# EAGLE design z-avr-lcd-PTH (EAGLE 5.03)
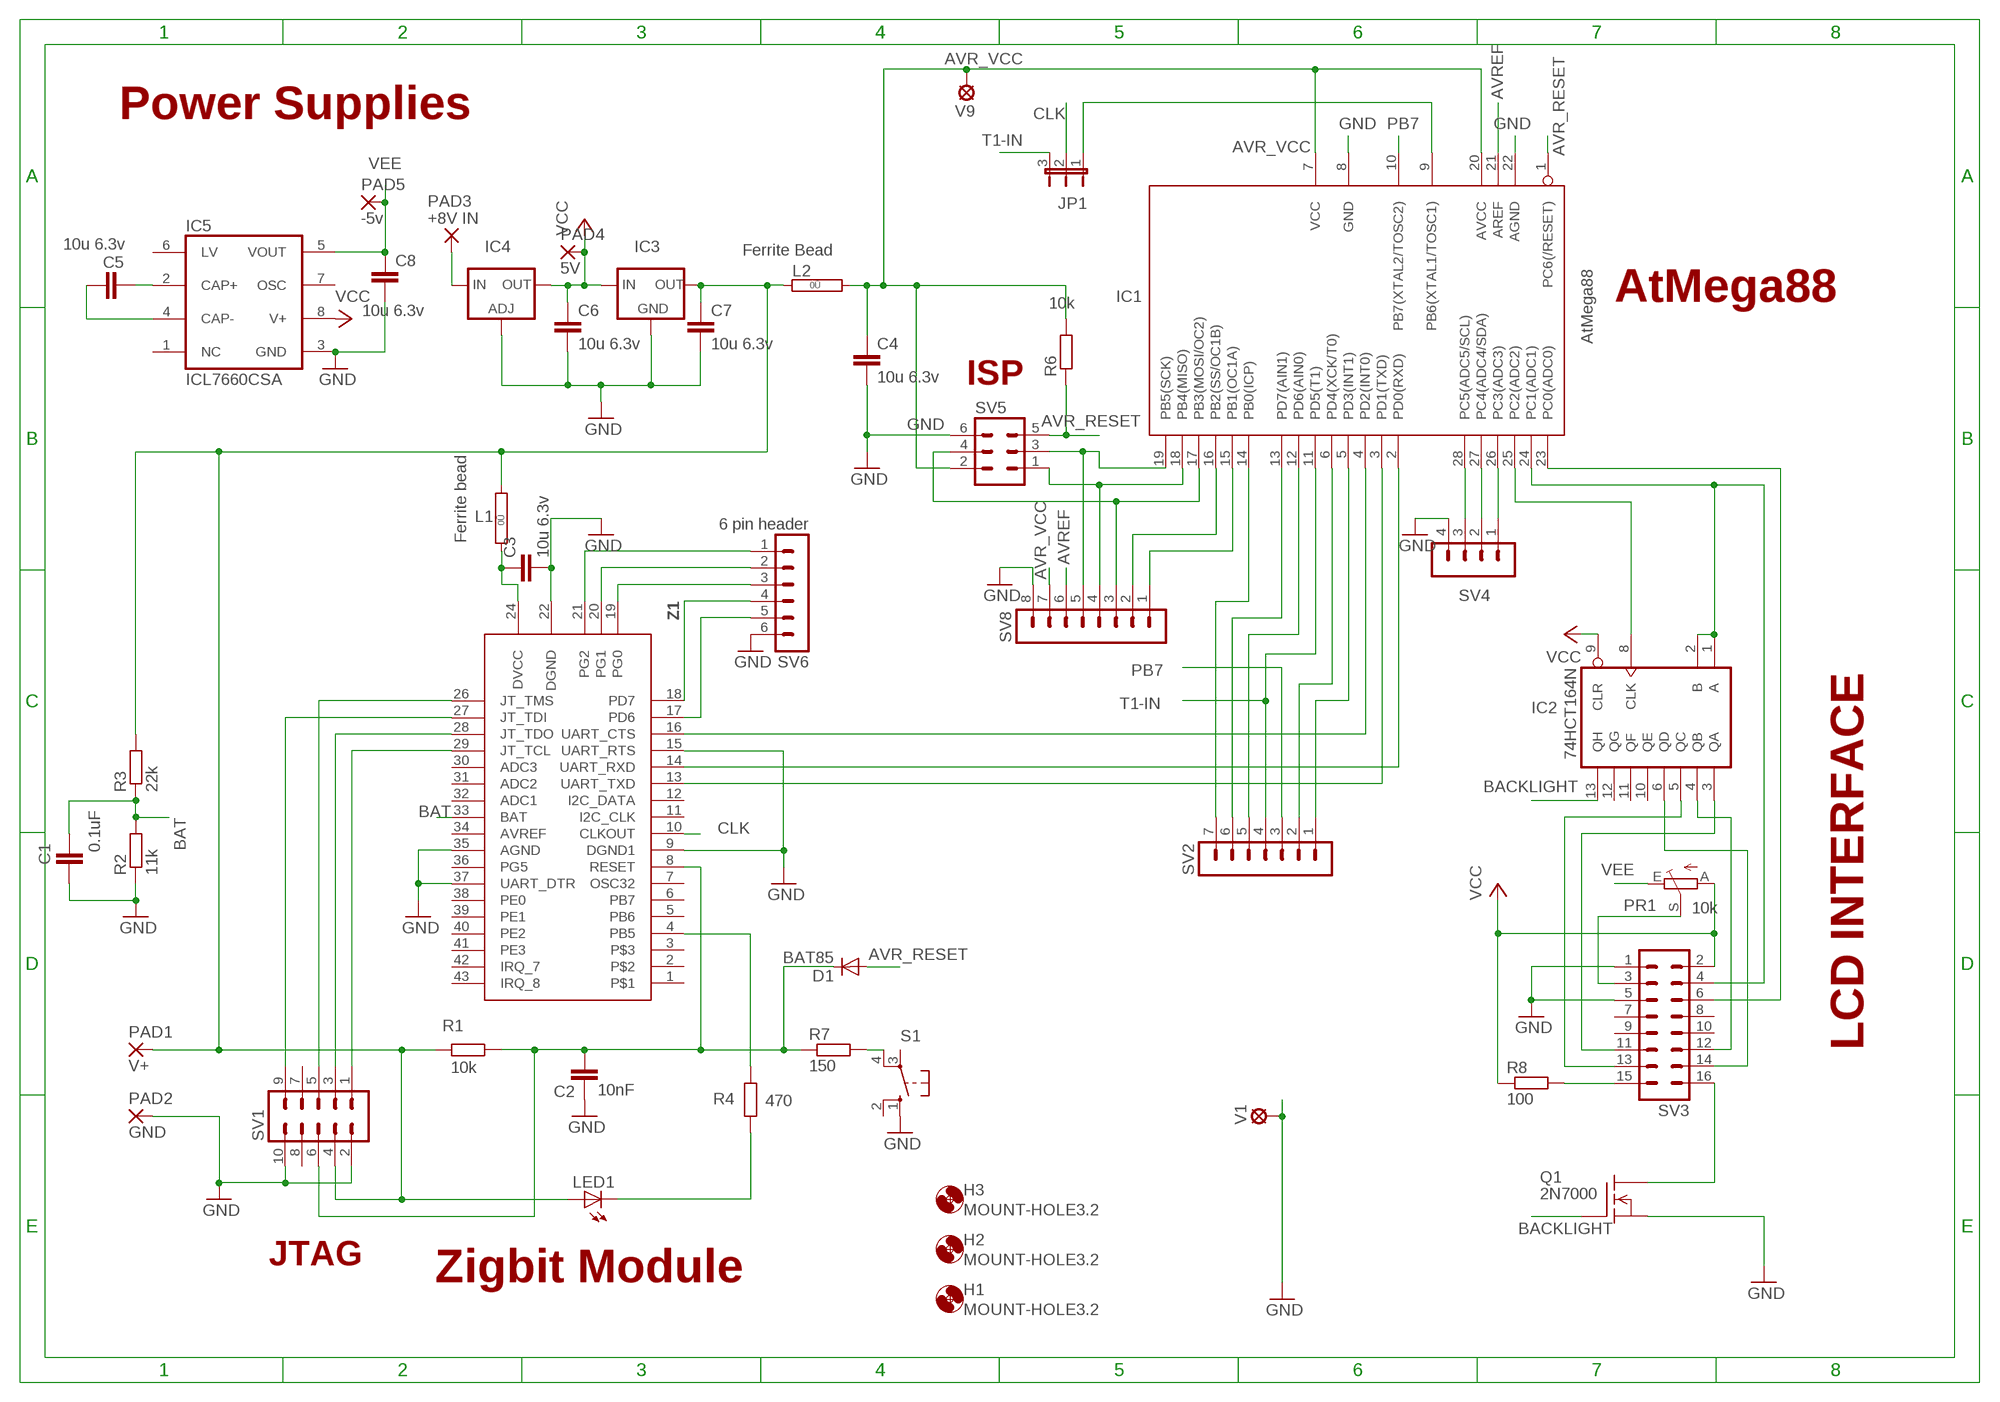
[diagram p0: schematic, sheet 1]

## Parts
C1  0.1uF  C5P  [C050-030-075]
C2  10nF  C5P  [C050-030-075]
C3  10u 6.3v  C-EUC1206  [C1206]
C4  10u 6.3v  C-EUC1206  [C1206]
C5  10u 6.3v  C-EUC1206  [C1206]
C6  10u 6.3v  C-EUC1206  [C1206]
C7  10u 6.3v  C-EUC1206  [C1206]
C8  10u 6.3v  C-EUC1206  [C1206]
D1  BAT85  1N4148  [DO34-7]
H1  MOUNT-HOLE3.2  [3,2]
H2  MOUNT-HOLE3.2  [3,2]
H3  MOUNT-HOLE3.2  [3,2]
IC1  AtMega88  MEGA8-P  [DIL28-3]
IC2  74HCT164N  74ACT164N  [DIL14]
IC3  MC1702-3302E/TO 3.3V LDO VREG  XC63FPT  [TO92]
IC4  LD117ADT50TR  [DPACK]
IC5  ICL7660CSA  [SO08]
JP1  3 way Jumper  JP2E  [JP2]
L1  Ferrite bead  0R  [0R/10]
L2  Ferrite Bead  JUMPER_0R  [JUMPER_0R/10]
LED1  3MM red LED  LED-3MM3MM  [HLMP-D105]
PAD1  V+  TERMINAL-PAD  [2,54/1,1]
PAD2  GND  TERMINAL-PAD  [2,54/1,1]
PAD3  +8V IN  PAD-TERMINAL  [2,54/1,1]
PAD4  5V  TERMINAL-PAD  [2,54/1,1]
PAD5  -5v  TERMINAL-PAD  [2,54/1,1]
PR1  10k  VAR_RESISTOR_TRIMS63P  [S63P]
Q1  2N7000  [TO92]
R1  10k  R  [0207/10]
R2  11k  R  [0207/10]
R3  22k  R  [0207/10]
R4  470  R  [0207/10]
R6  10k  R  [0207/10]
R7  150  R  [0207/10]
R8  100  R  [0207/10]
S1  BW3-1000 PCB pushbutton  10-XX  [B3F-10XX]
SV1  10 way IDC male horiz mnt  ML10L  [ML10L]
SV2  7 way pin header  MA07-1  [MA07-1]
SV3  16 way IDC male horiz mnt  ML16L  [ML16L]
SV4  4 way pin header  MA04-1  [MA04-1]
SV5  6 way male IDC horiz mnt  ML6L  [ML6L]
SV6  6 pin header  MA06-1  [MA06-1]
SV8  8 way pin header  MA08-1  [MA08-1]
V1  HOLE-VIA"  [1,6/0,8]
V9  HOLE-VIA"  [1,6/0,8]
Z1  ZDM-A1281-A2N  [ZIGSMD]

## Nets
AVR_RESET: D1.A IC1.1(PC6(/RESET)) R6.1 SV5.5
AVR_VCC [supply]: C4.1 IC1.7(VCC) IC1.20(AVCC) L2.2 R6.2 SV5.2 SV8.7 V9.1(MP)
AVREF: IC1.21(AREF) SV8.6
BACKLIGHT: IC2.13(QH) Q1.2(G)
BAT: C1.2 R2.2 R3.1 Z1.33(BAT)
CLK: JP1.2 Z1.10(CLKOUT)
GND: C1.1 C2.1 C3.2 C4.2 C6.2 C7.2 C8.2 IC1.8(GND) IC1.22(AGND) IC3.1(GND) IC4.1(ADJ) IC5.3(GND) PAD2.1(P) Q1.3(S) R2.1 S1.1(S) SV1.2 SV1.10 SV3.1 SV3.5 SV4.4 SV5.6 SV6.6 SV8.8 V1.1(MP) Z1.9(DGND1) Z1.15(UART_RTS) Z1.22(DGND) Z1.35(AGND) Z1.37(UART_DTR)
N$1: IC1.18(PB4(MISO)) SV5.1 SV8.4
N$2: IC1.19(PB5(SCK)) SV5.3 SV8.5
N$3: IC1.24(PC1(ADC1)) IC2.1(A) IC2.2(B) SV3.4
N$4: IC1.25(PC2(ADC2)) IC2.8(CLK)
N$5: IC1.28(PC5(ADC5/SCL)) SV4.3
N$6: R7.2 S1.4(P1)
N$7: IC1.27(PC4(ADC4/SDA)) SV4.2
N$8: IC1.17(PB3(MOSI/OC2)) SV5.4 SV8.3
N$9: SV1.5 Z1.26(JT_TMS)
N$10: SV1.1 Z1.29(JT_TCL)
N$11: SV1.3 Z1.28(JT_TDO)
N$12: IC1.26(PC3(ADC3)) SV4.1
N$13: C2.2 D1.C R1.2 R7.1 SV1.6 Z1.8(RESET)
N$14: IC2.6(QD) SV3.14
N$15: IC1.23(PC0(ADC0)) SV3.6
N$16 [supply]: C7.1 IC3.3(OUT) L1.2 L2.1 LED1.A PAD1.1(P) R1.1 R3.2 SV1.4
N$17: C5.1 IC5.2(CAP+)
N$18: IC1.4(PD2(INT0)) Z1.16(UART_CTS)
N$19: PR1.S SV3.3
N$20: IC1.2(PD0(RXD)) Z1.14(UART_RXD)
N$21: IC1.3(PD1(TXD)) Z1.13(UART_TXD)
N$22: IC2.3(QA) SV3.11
N$23: IC2.4(QB) SV3.12
N$24: IC2.5(QC) SV3.13
N$25: C5.2 IC5.4(CAP-)
N$26: R8.2 SV3.15
N$27: Q1.1(D) SV3.16
N$28: R4.2 Z1.4(PB5)
N$29 [supply]: IC4.3(IN) PAD3.1(P)
N$30: LED1.K(C) R4.1
N$31: SV1.9 Z1.27(JT_TDI)
N$32: IC1.9(PB6(XTAL1/TOSC1)) JP1.1
N$33 [supply]: C3.1 L1.1 Z1.24(DVCC)
N$34: SV6.1 Z1.21(PG2)
N$35: SV6.2 Z1.20(PG1)
N$36: SV6.3 Z1.19(PG0)
N$37: IC1.5(PD3(INT1)) SV2.1
N$38: IC1.15(PB1(OC1A)) SV8.1
N$39: IC1.16(PB2(SS/OC1B)) SV8.2
N$40: IC1.12(PD6(AIN0)) SV2.5
N$41: IC1.13(PD7(AIN1)) SV2.6
N$42: IC1.14(PB0(ICP)) SV2.7
N$43: SV6.4 Z1.18(PD7)
N$44: IC1.6(PD4(XCK/T0)) SV2.2
N$45: SV6.5 Z1.17(PD6)
PB7: IC1.10(PB7(XTAL2/TOSC2)) SV2.3
T1-IN: IC1.11(PD5(T1)) JP1.3 SV2.4
VCC [supply]: C6.1 IC2.9(CLR) IC3.2(IN) IC4.4(OUT) IC5.8(V+) PAD4.1(P) PR1.A R8.1 SV3.2
VEE: C8.1 IC5.5(VOUT) PAD5.1(P) PR1.E
Unconnected: IC2.10(QE) IC2.11(QF) IC2.12(QG) IC5.1(NC) IC5.6(LV) IC5.7(OSC) S1.2(S1) S1.3(P) SV1.7 SV1.8 SV3.7 SV3.8 SV3.9 SV3.10 Z1.1 Z1.2 Z1.3 Z1.5(PB6) Z1.6(PB7) Z1.7(OSC32) Z1.11(I2C_CLK) Z1.12(I2C_DATA) Z1.30(ADC3) Z1.31(ADC2) Z1.32(ADC1) Z1.34(AVREF) Z1.36(PG5) Z1.38(PE0) Z1.39(PE1) Z1.40(PE2) Z1.41(PE3) Z1.42(IRQ_7) Z1.43(IRQ_8)

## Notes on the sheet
- Power Supplies
- AtMega88
- ISP
- LCD INTERFACE
- JTAG
- Zigbit Module

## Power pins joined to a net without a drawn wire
GND: IC2.7(GND)
VCC: IC2.14(VCC)

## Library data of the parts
C1 C2 = ee2parts:C: Capacitor
C3-C8 = rcl:C-EU: CAPACITOR, European symbol
D1 = ee2parts:1N4148: DIODE
H1-H3 = holes:MOUNT-HOLE: MOUNTING HOLE with drill center marker
IC1 = atmel:MEGA8-P: MICROCONTROLLER 8 Kbytes FLASH, 1 kbytes SRAM, 512 bytes EEPROM, USART, 4-channel 10 bit ADC, 2-channel 8 bit ADC Pin compatible with Atmega48, ATMega88, ATMega168 Source: avr.lbr
IC2 = 74xx-eu:74*164: 8-bit parallel out SHIFT REGISTER
IC3 = v-reg:XC63FP: Positiv Voltage Regulators www.torex.co.jp/english/product/pro02/pdf/0201_xc62fp.pdf
IC4 = v-reg:LD117A?*: Low drop fixed and adjustable positive voltage regulators 1 A Source: http://www.st.com/stonline/products/literature/ds/7194/ld1117axx.pdf
IC5 = maxim:ICL7660CSA: VOLTAGE CONVERTER
JP1 = jumper:JP2E: JUMPER
L1 = jumper:0R: Bridge 0R 10mm
L2 = z-avr-lcd-noPTH:JUMPER_0R: Bridge 0R 10mm
LED1 = ee2parts:LED-3MM: LED
PAD1 PAD2 PAD4 PAD5 = ee2parts:TERMINAL-PAD: LARGE THROUGH-HOLE PAD
PAD3 = ee2parts:PAD-TERMINAL: LARGE THROUGH-HOLE PAD
PR1 = ee2parts:VAR_RESISTOR_TRIM: Variable resistor / potentiometer Trimmer potentiometer - Note that slider to end makes variable resistance
Q1 = z-avr-lcd-noPTH:2N7000: N-Channel Enhancement MOSFET 200V; 0,16A; 11Ohm
R1-R4 R6-R8 = ee2parts:R: Resistor
S1 = switch-omron:10-XX: OMRON SWITCH
SV1 = con-ml:ML10L: HARTING
SV2 = con-lstb:MA07-1: PIN HEADER
SV3 = con-ml:ML16L: HARTING
SV4 = con-lstb:MA04-1: PIN HEADER
SV5 = con-ml:ML6L: HARTING
SV6 = con-lstb:MA06-1: PIN HEADER
SV8 = con-lstb:MA08-1: PIN HEADER
V1 V9 = ee2parts:HOLE-VIA: FIXED VIA
Z1 = ee2parts:ZDM-A1281-A2

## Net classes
1 supply: width 0.889 mm

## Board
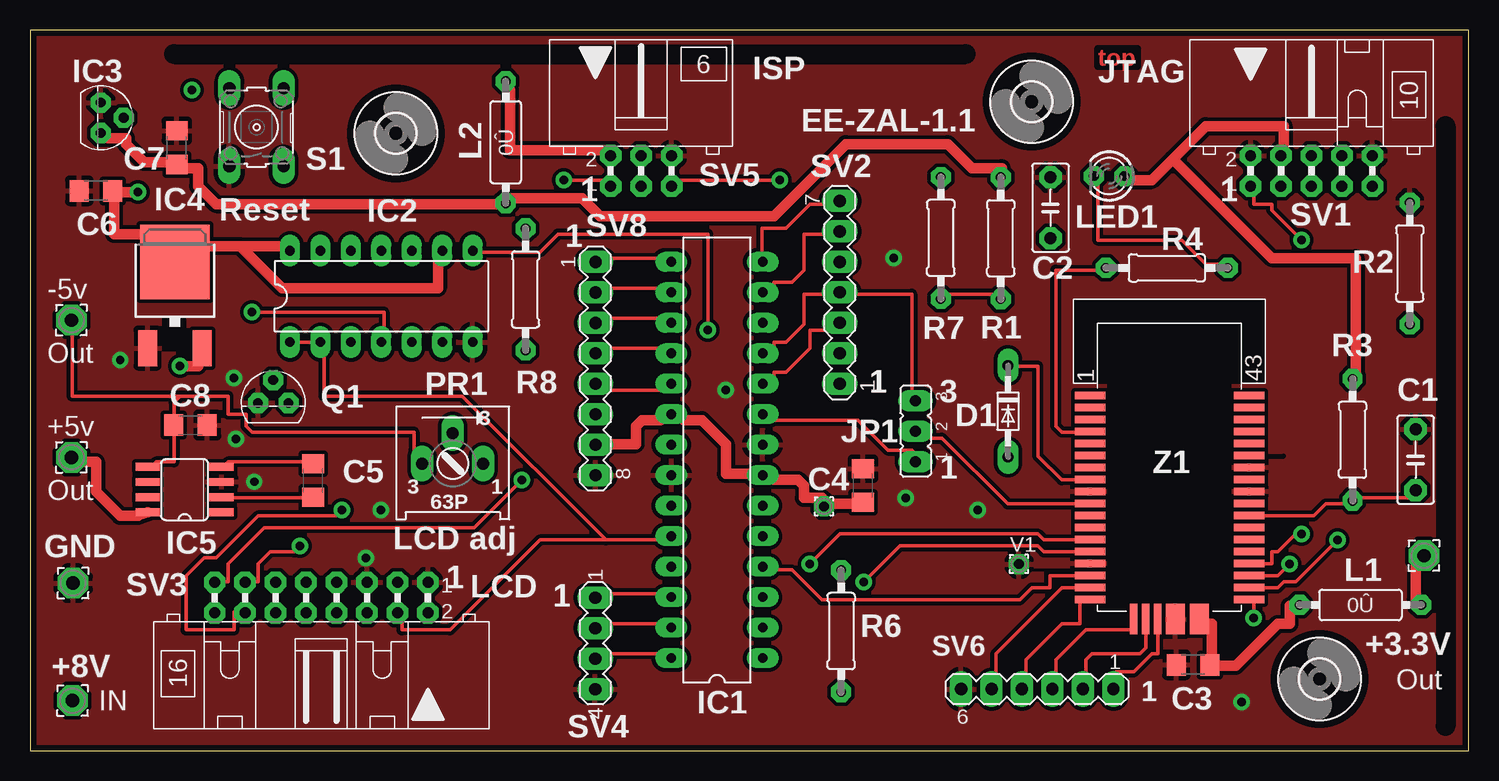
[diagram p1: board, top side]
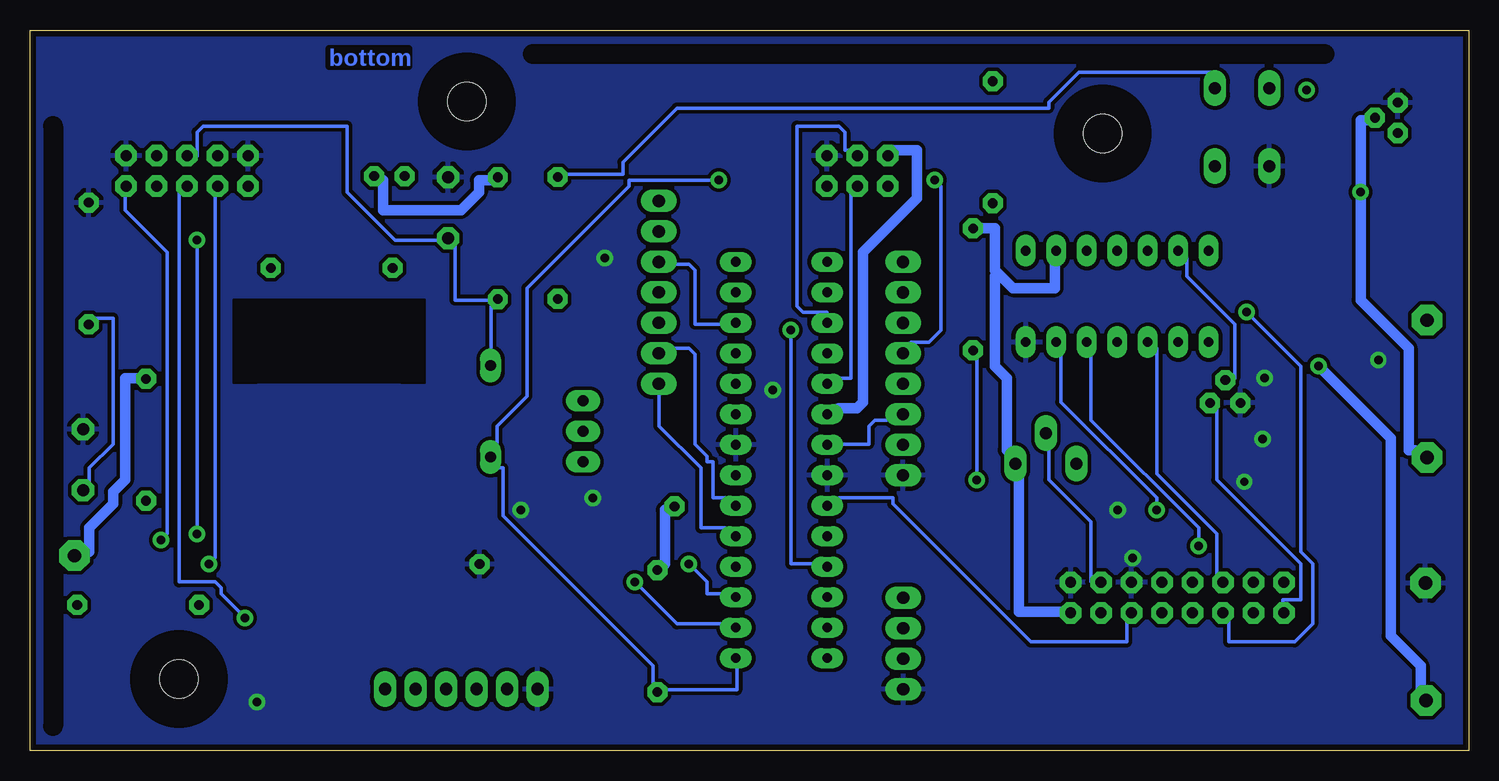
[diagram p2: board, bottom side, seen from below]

Size 119.92 x 60.07 mm. Coordinates in mm from the lower left corner, seen from the top.
Outline: 0,0 119.92,0 119.92,60.07 0,60.07 0,0
Copper layers (1*16): Top 0.035mm / dielectric 1.5mm / Bottom 0.035mm
Design rules "zigbit_rules *": minimum track width 12mil, minimum drill 0.7mm, track to track 12mil, track to pad 12mil, pad to pad 12mil, via to via 12mil, smd to smd 0mil, copper to edge 20mil, drill to drill 10mil, minimum pad ring 17mil, minimum via ring 13mil, stop-mask expansion 0mil, vias tented up to drill 0mil, thermal gap 15mil
tRestrict: area 11,33.3 to 13,36.1; 4 lines
bRestrict: 2 lines

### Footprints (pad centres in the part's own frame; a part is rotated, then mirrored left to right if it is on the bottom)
C050-030-075 = drill 1 octagon: 1 -2.54,0; 2 2.54,0
C1206 = smd 1.6 x 1.8: 1 -1.4,0; 2 1.4,0
DO34-7 = drill 0.9 long: A 3.81,0; C -3.81,0
3,2 = hole 3.2: 0,0
DIL28-3 = drill 0.813 long: 1 -16.51,-3.81; 2 -13.97,-3.81; 3 -11.43,-3.81; 4 -8.89,-3.81; 5 -6.35,-3.81; 6 -3.81,-3.81; 7 -1.27,-3.81; 8 1.27,-3.81; 9 3.81,-3.81; 10 6.35,-3.81; 11 8.89,-3.81; 12 11.43,-3.81; 13 13.97,-3.81; 14 16.51,-3.81; 15 16.51,3.81; 16 13.97,3.81; 17 11.43,3.81; 18 8.89,3.81; 19 6.35,3.81; 20 3.81,3.81; 21 1.27,3.81; 22 -1.27,3.81; 23 -3.81,3.81; 24 -6.35,3.81; 25 -8.89,3.81; 26 -11.43,3.81; 27 -13.97,3.81; 28 -16.51,3.81
DIL14 = drill 0.813 long: 1 -7.62,-3.81; 2 -5.08,-3.81; 3 -2.54,-3.81; 4 0,-3.81; 5 2.54,-3.81; 6 5.08,-3.81; 7 7.62,-3.81; 8 7.62,3.81; 9 5.08,3.81; 10 2.54,3.81; 11 0,3.81; 12 -2.54,3.81; 13 -5.08,3.81; 14 -7.62,3.81
TO92 = drill 0.813 octagon: 1 -1.27,0; 2 0,1.905; 3 1.27,0
DPACK = smd 1.6 x 3: 1 -2.28,-4.8; 3 2.28,-4.8 | smd 5.8 x 6.2: 4 0,2.38
SO08 = smd 0.66 x 2.032: 1 -1.905,-3.073; 2 -0.635,-3.073; 3 0.635,-3.073; 4 1.905,-3.073; 5 1.905,3.073; 6 0.635,3.073; 7 -0.635,3.073; 8 -1.905,3.073
JP2 = drill 0.914 long: 1 -2.54,0; 2 0,0; 3 2.54,0
0R/10 = drill 0.813 pad 1.6 octagon: 1 -5.08,0; 2 5.08,0
JUMPER_0R/10 = drill 0.813 pad 1.6 octagon: 1 -5.08,0; 2 5.08,0
HLMP-D105 = drill 0.8 octagon: A -1.27,0; K 1.27,0
2,54/1,1 = drill 1.118 pad 2.54 octagon: 1 0,0
S63P = drill 1 long: A 2.54,0; E -2.54,0; S 0,2.54
TO92' = drill 0.813 octagon: 1 1.27,0; 2 0,1.905; 3 -1.27,0
0207/10 = drill 0.8 octagon: 1 -5.08,0; 2 5.08,0
B3F-10XX = drill 1.016 long: 1 -3.251,2.261; 2 3.251,2.261; 3 -3.251,-2.261; 4 3.251,-2.261
ML10L = drill 0.914 octagon: 1 -5.08,-1.27; 2 -5.08,1.27; 3 -2.54,-1.27; 4 -2.54,1.27; 5 0,-1.27; 6 0,1.27; 7 2.54,-1.27; 8 2.54,1.27; 9 5.08,-1.27; 10 5.08,1.27
MA07-1 = drill 1.016 long: 1 -7.62,0; 2 -5.08,0; 3 -2.54,0; 4 0,0; 5 2.54,0; 6 5.08,0; 7 7.62,0
ML16L = drill 0.914 octagon: 1 -8.89,-1.27; 2 -8.89,1.27; 3 -6.35,-1.27; 4 -6.35,1.27; 5 -3.81,-1.27; 6 -3.81,1.27; 7 -1.27,-1.27; 8 -1.27,1.27; 9 1.27,-1.27; 10 1.27,1.27; 11 3.81,-1.27; 12 3.81,1.27; 13 6.35,-1.27; 14 6.35,1.27; 15 8.89,-1.27; 16 8.89,1.27
MA04-1 = drill 1.016 long: 1 -3.81,0; 2 -1.27,0; 3 1.27,0; 4 3.81,0
ML6L = drill 0.914 octagon: 1 -2.54,-1.27; 2 -2.54,1.27; 3 0,-1.27; 4 0,1.27; 5 2.54,-1.27; 6 2.54,1.27
MA06-1 = drill 1.016 long: 1 -6.35,0; 2 -3.81,0; 3 -1.27,0; 4 1.27,0; 5 3.81,0; 6 6.35,0
MA08-1 = drill 1.016 long: 1 -8.89,0; 2 -6.35,0; 3 -3.81,0; 4 -1.27,0; 5 1.27,0; 6 3.81,0; 7 6.35,0; 8 8.89,0
1,6/0,8 = drill 0.813 pad 1.6 octagon: 1 0,0
ZIGSMD = smd 0.635 x 2.54: 1 7,6.635; 2 6,6.635; 3 5,6.635; 4 4,6.635; 5 3,6.635; 6 2,6.635; 7 1,6.635; 8 0,6.635; 9 -1,6.635; 10 -2,6.635; 11 -3,6.635; 12 -4,6.635; 13 -5,6.635; 14 -6,6.635; 15 -7,6.635; 16 -8,6.635; 17 -9,6.635; 18 -10,6.635; 26 -10,-6.635; 27 -9,-6.635; 28 -8,-6.635; 29 -7,-6.635; 30 -6,-6.635; 31 -5,-6.635; 32 -4,-6.635; 33 -3,-6.635; 34 -2,-6.635; 35 -1,-6.635; 36 0,-6.635; 37 1,-6.635; 38 2,-6.635; 39 3,-6.635; 40 4,-6.635; 41 5,-6.635; 42 6,-6.635; 43 7,-6.635 | smd 2.54 x 0.635: 19 -11.635,3; 20 -11.635,2; 21 -11.635,1 | smd 2.54 x 1.6: 22 -11.635,-0.5; 24 -11.635,-2.5

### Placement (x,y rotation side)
C1  115.5,24.26 270 top
C2  85.07,45.26 270 top
C3  96.96,7.16 180 top
C4  69.44,22.11 90 top
C5  23.61,22.52 90 top
C6  5.5,46.66 180 top
C7  12.24,50.27 90 top
C8  13.38,27.15 0 top
D1  81.53,28.3 270 top
H1  107.5,5.99 0 top
H2  83.5,54.1 0 top
H3  30.5,51.46 0 top
IC1  57.27,24.24 90 top
IC2  29.29,37.87 0 top
IC3  5.9,52.75 270 top
IC4  12.08,38.35 0 top
IC5  12.89,21.77 90 top
JP1  73.82,26.64 90 top
L1  110.91,12.16 0 top
L2  39.66,50.72 90 top
LED1  89.96,47.89 180 top
PAD1  116.2,16.26 0 top
PAD2  3.59,13.98 90 top
PAD3  3.55,4.18 0 top
PAD4  3.45,24.45 0 top
PAD5  3.45,35.88 0 top
PR1  35.24,23.94 0 top
Q1  2N7000  [TO92']  20.28,28.99 0 top
R1  80.92,42.72 270 top
R2  115.02,40.61 270 top
R3  110.25,25.92 90 top
R4  94.77,40.24 180 top
R6  67.62,9.98 90 top
R7  75.93,42.74 90 top
R8  41.31,38.45 270 top
S1  18.88,51.97 90 top
SV1  106.83,48.33 0 top
SV2  67.51,38.2 90 top
SV3  24.28,12.77 180 top
SV4  47.12,8.95 270 top
SV5  50.95,48.33 0 top
SV6  83.97,5.15 180 top
SV8  47.14,31.85 270 top
V1  82.45,15.56 0 top
V9  66.19,20.37 0 top
Z1  94.99,22.61 90 top

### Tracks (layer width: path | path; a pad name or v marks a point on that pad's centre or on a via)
AVR_RESET  (via drill 0.7)
  Top 0.305: v62.5,47.57 54,47.57 SV5.5
  Bottom 0.305: IC1.1 61,7.07 61,5.07 67,5.07 R6.1 68,5.57 68,7.07 80.5,19.57 80.5,23.57 81,23.57 D1.A 81,25.57 81,27.07 78.5,29.57 78.5,38.57 70,47.07 70,47.57 v62.5,47.57
AVR_VCC
  Top 0.889: L2.2 40,55.07 40,50.07 48,50.07 SV5.2 | SV8.7 48.5,25.57 50.5,25.57 50.5,27.07 51,27.57 52.5,27.57 IC1.20 54.5,27.57 56,27.57 58,25.57 58,23.07 60,23.07 IC1.7 62,22.57 64,22.57 64.5,22.07 64.5,21.07 66,21.07 V9.1 67,20.57 69,20.57 C4.1
  Bottom 0.889: R6.2 67,15.57 67,20.07 V9.1 | SV5.2 48,50.07 46,50.07 46,46.07 50.5,41.57 50.5,29.07 51,28.57 52.5,28.57 IC1.20
AVREF
  Bottom 0.305: IC1.21 52.5,25.57 50,25.57 50,27.07 49.5,27.57 48.5,27.57 SV8.6
BACKLIGHT
  Bottom 0.305: Q1.2 19.5,31.07 19.5,35.57 23.5,39.57 23.5,41.07 IC2.13
BAT
  Top 0.305: Z1.33 102.5,19.57 107,19.57 108,20.57 109.5,20.57 R3.1 111,21.07 115,21.07 C1.2
  Bottom 0.305: R2.2 114.5,36.07 113,36.07 113,25.57 115,23.57 115,22.07 C1.2
CLK
  Top 0.305: Z1.10 87.5,20.57 81.5,20.57 76,26.07 75,26.07 JP1.2
GND  (via drill 0.7)
  other vias: 17.17,25.98 18.69,22.42 7.52,32.58 17,31.07 28,16.07 29.25,20.07 73,21.07 72,41.07 79,20.07 101,4.07 58,30.07
  pour Bottom: 0.25,59.82 119.67,59.82 119.67,0.25 0.25,0.25
  pour Top: 0.25,59.82 119.67,59.82 119.67,0.25 0.25,0.25
N$1  (via drill 0.7)
  Top 0.305: IC1.18 52.5,33.57 48.5,33.57 SV8.4 | v44.5,47.57 48,47.57 SV5.1
  Bottom 0.305: v44.5,47.57 44,47.07 44,35.07 45,34.07 46.5,34.07 46.5,33.57 SV8.4
N$2
  Top 0.305: IC1.19 52.5,30.07 48.5,30.07 SV8.5
  Bottom 0.305: SV5.3 51.5,46.57 51.5,31.07 52.5,31.07 IC1.19
N$3
  Top 0.305: IC2.1 22.5,34.07 23.5,34.07 IC2.2 24.5,33.07 24.5,29.57 36,29.57 48,17.57 | 48,17.57 42.5,17.57 35,10.07 31,10.07 31,11.07 SV3.4 | 48,17.57 52.5,17.57 IC1.24
N$4  (via drill 0.7)
  Top 0.305: v56.5,35.07 56.5,43.07 44,43.07 42.5,41.57 37.5,41.57 IC2.8
  Bottom 0.305: v56.5,35.07 56.5,15.57 54.5,15.57 IC1.25
N$5
  Top 0.305: IC1.28 52.5,8.07 48.5,8.07 SV4.3
N$6
  Bottom 0.305: R7.2 75.5,48.07 70.5,48.07 70.5,49.07 66,53.57 35,53.57 35,54.07 32.5,56.57 21.5,56.57 S1.4
N$7
  Top 0.305: IC1.27 52.5,10.57 48.5,10.57 SV4.2
N$8
  Top 0.305: IC1.17 52.5,36.07 48.5,36.07 SV8.3
  Bottom 0.305: SV5.4 51.5,50.07 52,50.07 52,51.57 52.5,52.07 56,52.07 56,37.07 55.5,36.57 53.5,36.57 53.5,36.07 IC1.17
N$9  (via drill 0.7)
  Top 0.305: v102,11.07 102,12.57 Z1.26
  Bottom 0.305: v102,11.07 104,13.07 104,13.57 104.5,14.07 107.5,14.07 107.5,46.57 SV1.5
N$10  (via drill 0.7)
  Top 0.305: v106,18.07 105.5,18.07 104,16.57 103.5,16.57 103.5,15.57 102.5,15.57 Z1.29 | v106,42.57 103.5,45.07 103.5,45.57 102,45.57 102,46.57 SV1.1
  Bottom 0.305: v106,18.07 v106,42.57
N$11  (via drill 0.7)
  Top 0.305: v105,15.57 104,14.57 102.5,14.57 Z1.28
  Bottom 0.305: v105,15.57 104.5,16.07 104.5,46.57 SV1.3
N$12
  Top 0.305: IC1.26 52.5,13.07 48.5,13.07 SV4.1
N$13
  Top 0.305: R1.2 80.5,38.07 76.5,38.07 R7.1 | Z1.8 87.5,22.57 86,22.57 84,24.57 84,32.07 82,32.07 D1.C
  Bottom 0.305: D1.C 81.5,33.07 81.5,37.07 R1.2 81.5,37.57 84.5,37.57 84.5,42.07 C2.2 86,42.57 89.5,42.57 93.5,46.57 93.5,52.07 105.5,52.07 106,51.57 106,49.57 SV1.6
N$14  (via drill 0.7)
  Top 0.305: v26,20.07 25.5,19.57 19,19.57 15.5,16.07 14.5,16.07 13,14.57 13,10.07 17,10.07 17,11.57 17.5,11.57 SV3.14
  Bottom 0.305: v26,20.07 26,21.07 34,29.07 34,33.07 IC2.6
N$15
  Bottom 0.305: IC1.23 52.5,21.07 48,21.07 48,20.57 36.5,9.07 28.5,9.07 28.5,11.07 SV3.6
N$16
  Top 0.889: IC3.3 6.5,51.07 8,51.07 8,50.57 9.5,49.07 11.5,49.07 C7.1 13,48.57 14,48.57 14,47.07 15.5,45.57 39,45.57 L2.1 40,46.07 46,46.07 47.5,44.57 62,44.57 68,50.57 76.5,50.57 78.5,48.57 81,48.57 R1.1 | L1.2 115.5,12.57 115.5,15.57 PAD1.1 | 95.25,49.32 93.5,47.57 92,47.57 LED1.A | 95.25,49.32 98,52.07 104.5,52.07 104.5,50.07 SV1.4 | R3.2 110.5,31.57 110.5,41.07 103.5,41.07 95.25,49.32
  Bottom 0.889: R3.2 111,31.07 112,31.07 112,22.57 113,21.57 113,20.57 115,18.57 115,16.57 PAD1.1 | R1.1 81.5,47.57 82.5,47.57 82.5,46.57 84,45.07 90.5,45.07 90.5,47.57 LED1.A
N$17
  Top 0.305: C5.1 23,21.07 16.5,21.07 IC5.2
N$18
  Top 0.305: Z1.16 87.5,14.57 85,14.57 85,13.57 83.5,13.57 82.5,12.57 66,12.57 63.5,15.07 62,15.07 IC1.4
N$19
  Bottom 0.305: SV3.3 31.5,14.07 31.5,19.07 35,22.57 35,25.07 PR1.S
N$20  (via drill 0.7)
  Top 0.305: v69.5,14.07 72.5,17.07 84,17.07 84.5,16.57 87.5,16.57 Z1.14
  Bottom 0.305: v69.5,14.07 66,10.57 62,10.57 IC1.2
N$21  (via drill 0.7)
  Top 0.305: v65,15.57 67.5,18.07 84,18.07 84.5,17.57 87.5,17.57 Z1.13
  Bottom 0.305: v65,15.57 63.5,14.07 63.5,13.07 62,13.07 IC1.3
N$22
  Bottom 0.305: IC2.3 26,33.57 26,23.07 21,18.07 21,14.57 SV3.11
N$23  (via drill 0.7)
  Top 0.305: v18.5,36.57 29.5,36.57 29.5,35.07 IC2.4
  Bottom 0.305: v18.5,36.57 14,32.07 14,16.57 13,15.57 13,10.57 14.5,9.07 20,9.07 20,11.07 SV3.12
N$24  (via drill 0.7)
  Top 0.305: v22.5,17.07 22,16.57 20,16.57 19,15.57 19,14.07 18.5,14.07 SV3.13
  Bottom 0.305: v22.5,17.07 22.5,18.57 31.5,27.57 31.5,33.07 IC2.5
N$25
  Top 0.305: C5.2 23,24.07 16.5,24.07 16,23.57 IC5.4
N$26  (via drill 0.7)
  Top 0.305: v41,22.57 37,18.57 19.5,18.57 16.5,15.57 16.5,14.07 16,14.07 SV3.15
  Bottom 0.305: v41,22.57 41,32.57 R8.2
N$27
  Bottom 0.305: Q1.1 21,28.57 21,22.57 14,15.57 14,12.57 15.5,12.57 15.5,12.07 SV3.16
N$28
  Top 0.305: Z1.4 87.5,26.57 86,26.57 85.5,27.07 85.5,40.07 89,40.07 R4.2
N$29  (via drill 0.7)
  Top 0.889: v12.5,32.07 14,32.07 IC4.3
  Bottom 0.889: v12.5,32.07 6.5,26.07 6.5,9.57 4,7.07 4,5.07 PAD3.1
N$30
  Top 0.305: LED1.K 89,47.07 89,42.57 96,42.57 98,40.57 99.5,40.57 R4.1
N$31  (via drill 0.7)
  Top 0.305: v109,17.57 105.5,14.07 104.5,14.07 104,13.57 102.5,13.57 Z1.27
  Bottom 0.305: v109,17.57 108.5,18.07 108.5,41.57 112,45.07 112,46.57 SV1.9
N$32
  Top 0.305: IC1.9 62,27.57 69,27.57 71.5,25.07 73.5,25.07 74,24.57 JP1.1
N$33
  Top 0.889: Z1.24 98,10.57 98.5,10.57 98.5,7.57 C3.1 99,7.07 100.5,7.07 104,10.57 105,10.57 105,12.07 L1.1
N$34
  Top 0.305: Z1.21 94,10.07 94,8.07 93.5,8.07 92,6.57 90.5,6.57 SV6.1
N$35
  Top 0.305: Z1.20 93,10.07 93,8.57 92.5,8.07 88.5,8.07 88,7.57 88,6.57 SV6.2
N$36
  Top 0.305: Z1.19 92,10.07 88,10.07 85.5,7.57 85.5,6.57 SV6.3
N$37
  Bottom 0.305: IC1.5 62,18.57 64,18.57 64,23.57 67.5,27.07 67.5,30.07 SV2.1
N$38
  Top 0.305: IC1.15 52.5,41.07 48.5,41.07 SV8.1
N$39
  Top 0.305: IC1.16 52.5,38.57 48.5,38.57 SV8.2
N$40
  Bottom 0.305: IC1.12 62,35.57 64.5,35.57 64.5,40.07 65,40.57 66.5,40.57 SV2.5
N$41
  Top 0.305: IC1.13 62,38.57 62,39.07 63.5,39.07 64.5,40.07 64.5,43.07 66.5,43.07 SV2.6
N$42
  Top 0.305: IC1.14 61,41.57 61,43.57 63,43.57 65,45.57 66.5,45.57 SV2.7
N$43
  Top 0.305: Z1.18 87.5,12.57 87.5,10.57 86,10.57 83,7.57 83,6.57 SV6.4
N$44
  Bottom 0.305: IC1.6 62,21.07 63,21.07 63,24.07 63.5,24.07 63.5,24.57 64.5,25.57 64.5,33.07 65,33.57 66.5,33.57 SV2.2
N$45
  Top 0.305: Z1.17 87.5,13.57 86,13.57 80.5,8.07 80.5,6.57 SV6.5
PB7
  Top 0.305: IC1.10 62,31.07 62,31.57 63,31.57 65,33.57 65,35.07 66.5,35.07 SV2.3
T1-IN
  Top 0.305: IC1.11 62,33.57 62,34.07 63,34.07 64.5,35.57 64.5,38.07 66.5,38.07 SV2.4 69,38.07 73.5,38.07 73.5,29.57 JP1.3
VCC  (via drill 0.7)
  Top 0.889: IC5.8 9,19.57 7.5,19.57 5.5,21.57 5.5,24.07 4.5,24.07 PAD4.1 | 17.5,42.07 14.5,42.07 IC4.4 9.5,43.07 7,43.07 7,46.07 C6.1 7.5,46.57 v9,46.57 | 17.5,42.07 21,42.07 IC2.14 | 17.5,42.07 21,38.57 34,38.57 34,40.57 IC2.9
  Bottom 0.889: SV3.2 34,11.57 37.5,11.57 37.5,22.57 PR1.A 38.5,25.07 38.5,31.07 39.5,32.07 39.5,39.57 39.25,39.82 | 39.25,39.82 38,38.57 34.5,38.57 34.5,40.57 IC2.9 | 39.25,39.82 39.5,40.07 39.5,43.57 40.5,43.57 R8.1 | IC3.2 8.5,52.57 9,52.57 v9,46.57 9,37.57 5,33.57 5,25.07 4.5,25.07 PAD4.1
VEE
  Top 0.305: IC5.5 10,23.57 10.5,24.07 12,24.07 12,26.57 C8.1 12,27.57 12,29.07 12.5,29.57 | 12.5,29.57 16.5,29.57 16.5,28.07 18,28.07 18,27.07 18.5,26.57 32,26.57 32,25.07 PR1.E | 12.5,29.57 3.5,29.57 3.5,35.07 PAD5.1
XX  (via drill 0.7)
  other vias: 13.5,55.07

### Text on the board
Top: top
Bottom: bottom
tNames: IC3 | ISP | JTAG | EE-ZAL-1.1 | S1 | 1 | 1 | Reset | 1 | -5v | Out | 1 | 3 | +5v | 1 | Out | LCD adj | 1 | LCD | 1 | +8V | +3.3V | Out | 1 | IN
